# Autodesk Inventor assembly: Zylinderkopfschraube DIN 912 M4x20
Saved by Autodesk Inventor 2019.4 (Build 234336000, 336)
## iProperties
Created: 2021-06
Part Number: Zylinderkopfschraube DIN 912 M4x20
Document SubType Name: Assembly
Designer: Administrator
Title: Zylinderkopfschraube DIN 912 M4x20 v2
Author: Administrator
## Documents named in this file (2)
- c:\worker\convert-fusion-r04\tmp\job-1\39\output\files\e1e84fd7-b652-4e3d-a1c7-f0a54bbc30a7\Zylinderkopfschraube DIN 912 M4x20 v2.iam
- c:\worker\convert-fusion-r04\tmp\job-1\39\output\files\e1e84fd7-b652-4e3d-a1c7-f0a54bbc30a7\HI_WUERTH 00824  20 cylinder head screw DIN 912 M4x20 8.8 BLK.ipt
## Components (1 placed, 1 different names)
1. HI_WUERTH 00824  20 cylinder head screw DIN 912 M4x20 8.8 BLK:1
